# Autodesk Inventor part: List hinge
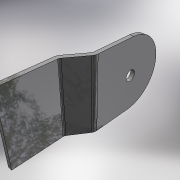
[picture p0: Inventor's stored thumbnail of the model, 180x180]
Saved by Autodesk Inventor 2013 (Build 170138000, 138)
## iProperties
Shininess: 64.0
Length Units: 11269
Angle Units: 11279
Time Units: 11290
Mass Units: 11283
Length Display Precision: 3
Angle Display Precision: 2
Compacted: True
Part Number: List hinge
Document SubType Name: Листовой материал
Created: 2004-12
Material: Stainless Steel, 440C
Designer: =<Author>
Manufacturer: Standard
Standards Organization: Custom
Description: =<Part Number>
Density: 7.75 g/cm^3
Sheet Metal Rule: По умолчанию
Mass: 304.468 g
Surface Area: 214.146 cm^2
Volume: 39.2862 cm^3
Density: 0.0
Volumn: 0.0
Area: 0.0
PropertySet Name: Model Information
Control State: 0
Master: False
Checked Out: False
Checked Out Date: 2008-10-15
Last Check In Date: 2008-10-15
Author: PVitaliy
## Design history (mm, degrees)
node "ФлнОтгиб1"
  sketch "Эскиз1"
    geometry: L1 (0, 50)-(0, 0); L2 (0, 50)-(14, 70); L3 (14, 70)-(14, 145)
    constraints: 6 end point, 1 parallel, 1 other
    dimensions: "d16" = 145 vertical distance of L3.end L1.end; "d17" = 14 distance between parallel lines of L3 L1; "d19" = 70 vertical distance of L2.end L1.end; "d20" = 20 vertical distance of L1.start L2.end
feature "Вырез1" dims "d13" = 4 (= Толщина), "d14" = 0
body "Solid1"
feature "Пластина1" dims "d6" = 70, "d7" = 4 (= Ширина_просечки), "d9" = 8 (= Минимальный_остаток), "d11" = 4 (= Радиус_гибки), "d12" = 4, "Толщина" = 4
feature "Изгиб1" dims "d7" = 4 (= Ширина_просечки), "d8" = 2 (= Глубина_просечки), "d9" = 8 (= Минимальный_остаток), "d10" = 4 (= Радиус_гибки), "d11" = 4 (= Радиус_гибки), "d12" = 4, "Толщина" = 4, "Зазор_стыка" = 0.01
sketch "Эскиз2"
  geometry: L1 (0, -73.739)-(70, -73.739) reference; L2 (70, -73.739)-(70, 0) reference; L3 (0, 0)-(70, 0) reference; L4 (0, -73.739)-(0, 0) reference; L5 (0, -145)-(70, -145) reference; C1 r 5.5 at (35, -35); A1 r 35 centre (35, -35) between (70, -35) and (0, -35)
  constraints: 3 tangent, 2 centre point, 2 point on circle, 2 point on line, 1 coincident
  dimensions: "d15" = 11 diameter of C1
other parameters: "Радиус_гибки" = 4 (= Толщина), "Ширина_просечки" = 4 (= Толщина), "Глубина_просечки" = 2 (= 0.5 x Толщина), "Размер_высечки" = 16 (= 4 x Толщина), "Минимальный_остаток" = 8 (= 2 x Толщина), "Радиус_перехода" = 4 (= Радиус_гибки), "JacobiRadiusSize" = 4 (= Толщина), "GapSize" = 4 (= Толщина)
